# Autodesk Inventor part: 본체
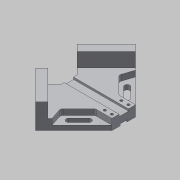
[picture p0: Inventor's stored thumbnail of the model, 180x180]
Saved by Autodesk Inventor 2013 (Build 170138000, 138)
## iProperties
Created: 2019-04
Part Number: 본체
Material: 알루미늄 6061
Document SubType Name: Modeling
Designer: Administrator
Density: 2.71 g/cm^3
Mass: 603.672 g
Surface Area: 425.327 cm^2
Volume: 222.757 cm^3
Author: Administrator
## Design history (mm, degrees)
sketch "스케치1"
  geometry: L1 (84.853, 0)-(35.355, 49.497); L2 (0, 84.853)-(-35.355, 49.497); L3 (-84.853, 0)-(-20, -64.853); L4 (0, -84.853)-(20, -64.853); L5 (84.853, 0)-(-84.853, 0); L6 (0, 84.853)-(0, -84.853); L7 (-35.355, 49.497)-(-14.005, 28.147); L8 (-14.005, 28.147)-(14.005, 28.147); L9 (14.005, 28.147)-(35.355, 49.497); L10 (-20, -64.853)-(20, -64.853); L11 (20, -64.853)-(84.853, 0); L12 (-20, -64.853)-(0, -84.853); L13 (-35.355, 49.497)-(-84.853, 0); L14 (35.355, 49.497)-(0, 84.853); 4 further points
  constraints: 28 end point, 8 parallel, 5 midpoint, 4 perpendicular, 2 horizontal, 2 vertical alignment, 1 equal length
  dimensions: "d0" = 120 distance of L1.start L2.start; "d2" = 50 distance of L2.start L2.end; "d3" = 40 distance of L3.end L4.end; "d4" = 93 distance between parallel lines of L8 L10; "d6" = 90 deg angle of L7 L13; "d7" = 90 deg angle of L1 L9
extrude "돌출1" new body sketch "스케치1" distance "d8" = 18; taper "d9" = 0 deg
sketch "스케치2"
  geometry: L1 (84.853, 0)-(35.355, 49.497) reference; L2 (35.355, 49.497)-(14.005, 28.147) reference; L3 (-14.005, 28.147)-(-35.355, 49.497) reference; L4 (-35.355, 49.497)-(-84.853, 0) reference; L5 (-84.853, 0)-(-20, -64.853) reference; L6 (20, -64.853)-(84.853, 0) reference; L7 (-74.246, -10.607)-(-24.749, 38.891); L8 (24.749, 38.891)-(74.246, -10.607); 1 further point
  constraints: 4 end point, 4 point on line, 2 perpendicular
  dimensions: "d10" = 15 distance between parallel lines of L7 L4; "d11" = 15 distance between parallel lines of L1 L8
extrude "돌출2" join sketch "스케치2" distance "d12" = 24; taper "d13" = 0 deg
sketch "스케치3"
  geometry: L1 (-74.246, -10.607)-(-20, -64.853) reference; L2 (-70.711, -14.142)-(-49.497, -7.071); L3 (-49.497, -7.071)-(-20, -36.569); L4 (-35.355, 49.497)-(-84.853, 0) reference; L5 (-20, -64.853)-(-20, -36.569); 1 further point
  constraints: 6 end point, 1 parallel, 1 point on line, 1 vertical
  dimensions: "d14" = 20 distance between parallel lines of L3 L1; "d16" = 20 distance from line of L2.start L4; "d17" = 30 distance from line of L2.end L4
extrude "돌출3" cut sketch "스케치3" distance "d18" = 10; taper "d19" = 0 deg
sketch "스케치4"
  geometry: L1 (-20, -64.853)-(-70.711, -14.142) reference; L2 (-52.679, -24.395)-(-35.709, -41.366); L3 (-46.315, -18.031)-(-29.345, -35.002); L4 (-84.853, 0)-(-20, -64.853) reference; L5 (-35.355, 49.497)-(-84.853, 0) reference; A1 r 4.5 centre (-49.497, -21.213) between (-46.315, -18.031) and (-52.679, -24.395); A2 r 4.5 centre (-32.527, -38.184) between (-35.709, -41.366) and (-29.345, -35.002); 1 further point
  constraints: 4 end point, 4 point on circle, 4 tangent, 2 centre point, 1 equal radius
  dimensions: "d20" = 10 distance from line of A1.centre L4; "d21" = 40 distance from line of A1.centre L5; "d22" = 24 distance of A2.centre A1.centre; "d23" = 9 distance between parallel lines of L3 L2; "d24" = 10 distance from line of A2.centre L1
extrude "돌출4" cut sketch "스케치4" stored distance "d25" = 10; taper "d26" = 0 deg
sketch "스케치5"
  geometry: L1 (14.005, 28.147)-(-14.005, 28.147) reference; L2 (-20, -64.853)-(20, -64.853) reference; L3 (-8, 28.147)-(-8, -64.853); L4 (8, 28.147)-(8, -64.853); 1 further point
  constraints: 4 end point, 4 point on line, 2 vertical, 1 parallel
  dimensions: "d27" = 16 distance between parallel lines of L4 L3; "d28" = 8 distance from line of point (0, 0) L3
extrude "돌출5" cut sketch "스케치5" distance "d29" = 3.5; taper "d30" = 0 deg
sketch "스케치6"
  geometry: L1 (20, -64.853)-(-20, -64.853) reference; L2 (-14.005, 28.147)-(14.005, 28.147) reference; L3 (-6, 28.147)-(-6, -64.853); L4 (6, -64.853)-(6, 28.147); 1 further point
  constraints: 4 end point, 4 point on line, 2 vertical, 1 parallel
  dimensions: "d31" = 12 distance between parallel lines of L4 L3; "d32" = 6 distance from line of L4 point (0, 0)
extrude "돌출6" cut sketch "스케치6" distance "d33" = 3; taper "d34" = 0 deg
sketch "스케치7"
  geometry: L1 (20, -64.853)-(70.711, -14.142) reference; L2 (20, -64.853)-(8, -64.853) reference; 5 further points
  constraints: 2 horizontal alignment, 2 vertical alignment
  dimensions: "d35" = 28 distance of point (14, -58.853) point (-14, -58.853); "d37" = 6 distance from line of point (14, -58.853) L2; "d38" = 12 distance of point (14, -46.853) point (14, -58.853); "d39" = 14 horizontal distance of point (0, 0) point (-14, -58.853)
hole "구멍1" sketch "스케치7" at (-14, -58.853), (-14, -46.853), (14, -58.853), (14, -46.853) diameter "d40" = 4.5; stored, may be unused: countersink angle "d44" = 90 deg, drill point angle "d46" = 118 deg; dims "d41" = 6, "d42" = 8, "d43" = 10, "d45" = 8
fillet "모깎기1" dims "d47" = 5
node "솔리드1"
mirror "대칭1"
